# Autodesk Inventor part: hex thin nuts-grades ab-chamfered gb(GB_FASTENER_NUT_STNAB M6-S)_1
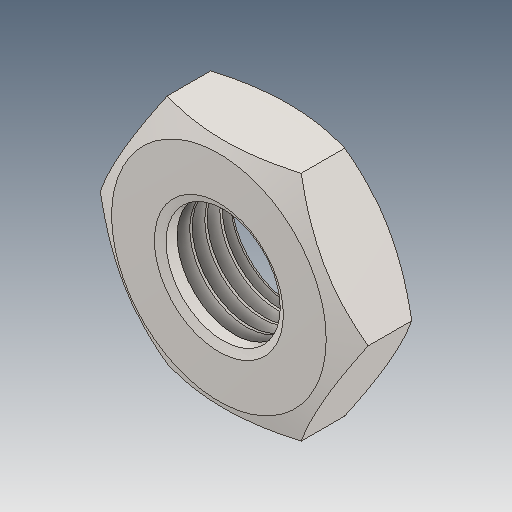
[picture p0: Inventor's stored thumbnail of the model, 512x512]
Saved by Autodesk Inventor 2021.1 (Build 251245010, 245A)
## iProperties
Created: 2021-05
Part Number: hex thin nuts-grades ab-chamfered gb(GB_FASTENER_NUT_STNAB M6-S)_1
Material: Ogólny
Document SubType Name: Modeling
Designer: user
Density: 1 g/cm^3
Appearance: Domyślna
Author: user
Revision Number: ÈÎºÎ
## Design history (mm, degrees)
feature "ÊäÈë1"
node "Bryła1"
